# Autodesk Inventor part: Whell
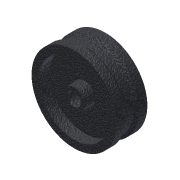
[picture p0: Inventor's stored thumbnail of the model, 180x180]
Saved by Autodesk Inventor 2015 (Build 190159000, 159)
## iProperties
Created: 2013-01
Part Number: Whell
Material: Iron, Cast
Document SubType Name: Modeling
Designer: CADCIM
Density: 7.25 g/cm^3
Appearance: Iron - Cast
Mass: 68.2997 g
Surface Area: 59.6738 cm^2
Volume: 9.42065 cm^3
Author: CADCIM
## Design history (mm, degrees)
sketch "Sketch1"
  geometry: L1 (0, 0)-(24, 0); L2 (15, -3.125)-(15, -5); L3 (0, -3.125)-(0, -5); L4 (0, -16.5)-(0, -20); L5 (14.702, -16.5)-(14.702, -19.781); L6 (5, -5)-(5, -16.5); L7 (10, -5)-(10, -16.5); L8 (0, -5)-(5, -5); L9 (10, -5)-(15, -5); L10 (0, -16.5)-(5, -16.5); L11 (10, -16.5)-(14.702, -16.5); L12 (4, -20)-(5.493, -18.525); L13 (9.46, -18.525)-(10.702, -19.781); L14 (0, -20)-(4, -20); L15 (10.702, -19.781)-(14.702, -19.781); L16 (0, -3.125)-(15, -3.125); L17 (5.493, -18.525)-(9.46, -18.525)
  constraints: 34 end point, 9 parallel, 8 perpendicular, 1 horizontal
  dimensions: "d0" = 15 distance of L3.start L2.start; "d5" = 5 distance between parallel lines of L7 L6; "d6" = 5 distance between parallel lines of L3 L6; "d7" = 4 distance from line of L12.start L4; "d8" = 90 deg angle of L13 L12; "d9" = 4 distance of L5.end L13.end; "d13" = 16.5 distance between parallel lines of L1 L11; "d14" = 5 distance between parallel lines of L1 L9
revolve "Revolution1" sketch "Sketch1" stored, may be unused: angle "d16" = 90 deg
body "Solid1"
other parameters: "d1" = 3.125, "d2" = 5, "d3" = 16.5
